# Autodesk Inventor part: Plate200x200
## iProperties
Created: 2006-02
Part Number: Plate200x200
Document SubType Name: Modeling
Designer: 40664
Mass: 395.476 g
Surface Area: 886.032 cm^2
Volume: 395.476 cm^3
Density: 1 g/cm^3
CSToolsMass: 0.4
CSToolsVolume: 395476.0
CSToolsArea: 886.0
Author: 40664
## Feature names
1. Extrusion1
2. Hole1
